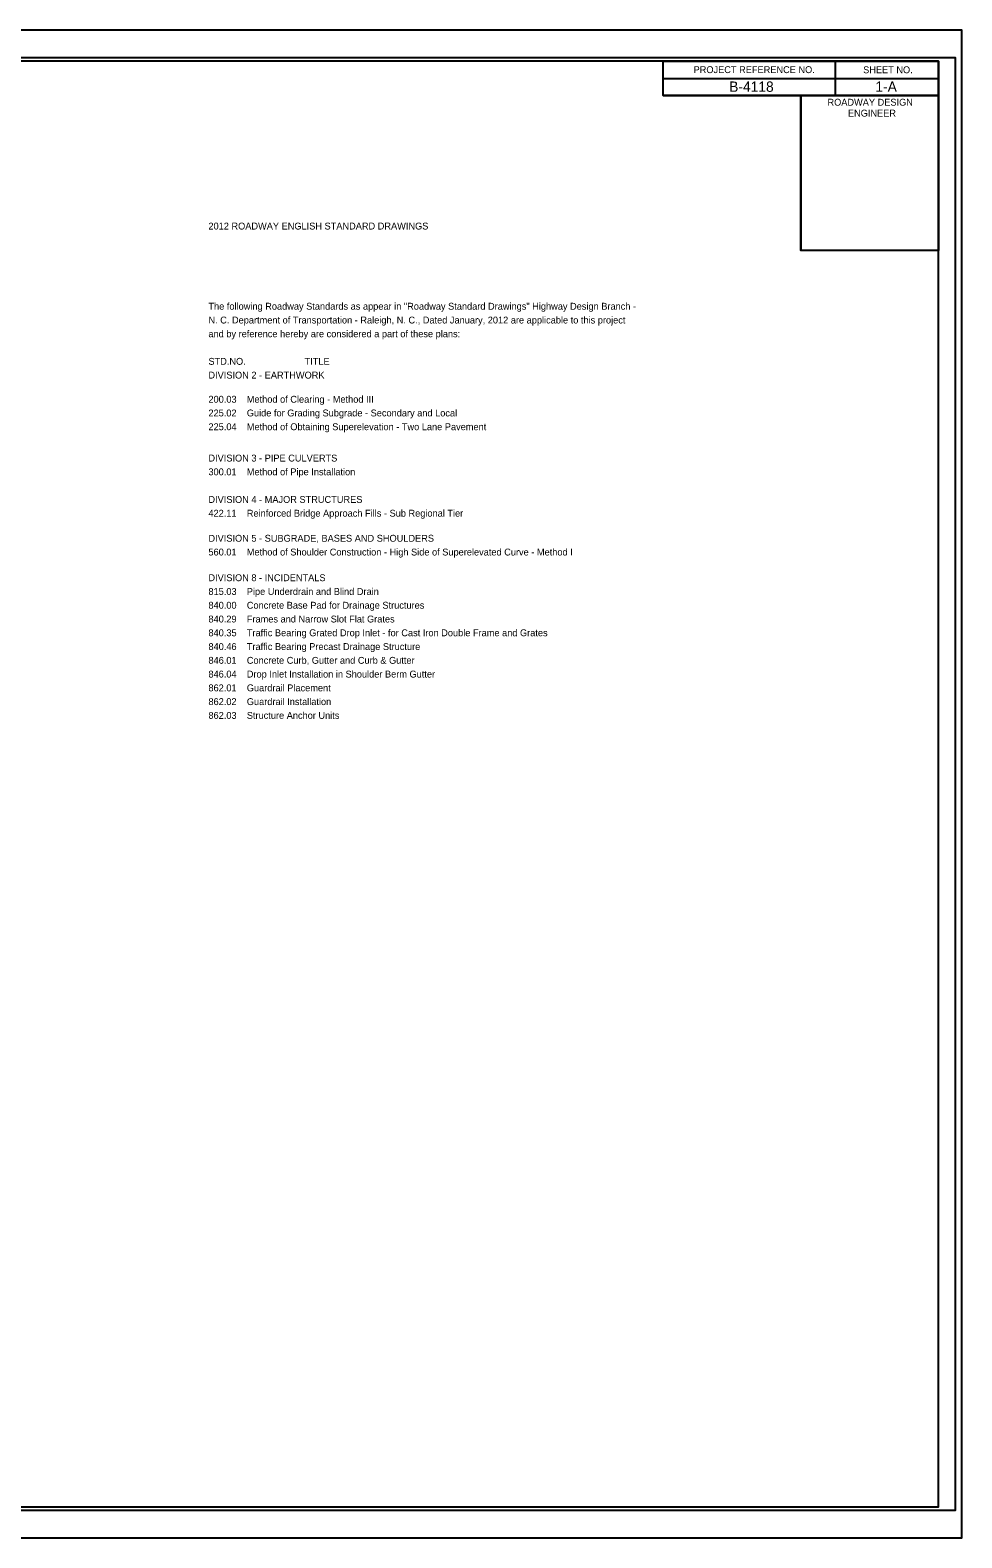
# Model space of a CAD drawing. Extents: x 573853.4 to 573887.1, y -53299.2 to -53277.3.
# Drawn here: x 573873.53 to 573887.06, y -53299.24 to -53277.34 of the extents above; entities that cross this region are included whole.
import ezdxf

# ---------------------------------------------------------------- set-up
doc = ezdxf.new("R2010")
doc.units = 0
for name, color, linetype in [('Prop Dimension Text', 7, 'Continuous'), ('Sheet Cutting Line CELL', 7, 'Continuous'), ('Sheet Data Field CELL', 7, 'Continuous'), ('Sheet Plan CELL', 7, 'Continuous'), ('Sheet Plot Border Inside CELL', 7, 'Continuous'), ('Sheet Plot Border Outside CELL', 7, 'Continuous')]:
    doc.layers.add(name, color=color, linetype=linetype)

msp = doc.modelspace()

# ---------------------------------------------------------------- linework, layer by layer
at = {"layer": 'Sheet Cutting Line CELL'}
for p, q in [((573887.06, -53277.34), (573853.39, -53277.34)), ((573853.39, -53299.24), (573887.06, -53299.24))]:
    msp.add_line(p, q, dxfattribs=at)
at = {"layer": 'Sheet Plan CELL'}
for p, q in [((573885.22, -53277.791), (573885.22, -53278.291)), ((573882.719, -53278.041), (573886.72, -53278.041)), ((573882.719, -53278.291), (573886.72, -53278.291)), ((573882.719, -53278.291), (573886.72, -53278.291)), ((573884.72, -53278.291), (573884.72, -53280.54))]:
    msp.add_line(p, q, dxfattribs=at)
for points in [[(573886.72, -53277.79), (573856.72, -53277.79), (573856.72, -53298.79), (573886.72, -53298.79)], [(573882.719, -53277.79), (573886.72, -53277.79), (573886.72, -53278.291), (573882.719, -53278.291)], [(573884.72, -53278.291), (573886.72, -53278.291), (573886.72, -53280.541), (573884.72, -53280.541)]]:
    msp.add_lwpolyline(points, close=True, dxfattribs=at)
at = {"layer": 'Sheet Plot Border Inside CELL'}
msp.add_lwpolyline([(573853.65, -53298.84), (573886.97, -53298.84), (573886.97, -53277.74), (573853.65, -53277.74)], close=True, dxfattribs=at)
at = {"layer": 'Sheet Plot Border Outside CELL'}
msp.add_lwpolyline([(573853.39, -53299.24), (573887.06, -53299.24), (573887.06, -53277.34), (573853.39, -53277.34)], close=True, dxfattribs=at)

# ---------------------------------------------------------------- texts
at = {"layer": 'Prop Dimension Text'}
for s, p in [('2012 ROADWAY ENGLISH STANDARD DRAWINGS', (573876.115, -53280.236)), ('The following Roadway Standards as appear in "Roadway Standard Drawings" Highway Design Branch -', (573876.115, -53281.401)), ('N. C. Department of Transportation - Raleigh, N. C., Dated January, 2012 are applicable to this project', (573876.115, -53281.601)), ('and by reference hereby are considered a part of these plans:', (573876.115, -53281.801)), ('STD.NO.                       TITLE', (573876.115, -53282.201)), ('DIVISION 2 - EARTHWORK', (573876.115, -53282.401)), ('200.03    Method of Clearing - Method III', (573876.115, -53282.752)), ('225.02    Guide for Grading Subgrade - Secondary and Local', (573876.115, -53282.951)), ('225.04    Method of Obtaining Superelevation - Two Lane Pavement', (573876.115, -53283.151)), ('DIVISION 3 - PIPE CULVERTS', (573876.115, -53283.606)), ('300.01    Method of Pipe Installation ', (573876.115, -53283.806)), ('DIVISION 4 - MAJOR STRUCTURES', (573876.115, -53284.207)), ('422.11    Reinforced Bridge Approach Fills - Sub Regional Tier', (573876.115, -53284.407)), ('DIVISION 5 - SUBGRADE, BASES AND SHOULDERS', (573876.115, -53284.771)), ('560.01    Method of Shoulder Construction - High Side of Superelevated Curve - Method I', (573876.115, -53284.971)), ('DIVISION 8 - INCIDENTALS', (573876.115, -53285.344)), ('815.03    Pipe Underdrain and Blind Drain', (573876.115, -53285.544)), ('840.00    Concrete Base Pad for Drainage Structures', (573876.115, -53285.744)), ('840.29    Frames and Narrow Slot Flat Grates', (573876.115, -53285.944)), ('840.35    Traffic Bearing Grated Drop Inlet - for Cast Iron Double Frame and Grates', (573876.115, -53286.144)), ('840.46    Traffic Bearing Precast Drainage Structure', (573876.115, -53286.344)), ('846.01    Concrete Curb, Gutter and Curb & Gutter', (573876.115, -53286.544)), ('846.04    Drop Inlet Installation in Shoulder Berm Gutter', (573876.115, -53286.744)), ('862.01    Guardrail Placement', (573876.115, -53286.944)), ('862.02    Guardrail Installation', (573876.115, -53287.144)), ('862.03    Structure Anchor Units', (573876.115, -53287.344))]:
    msp.add_text(s, height=0.1, dxfattribs=at).set_placement(p)
at = {"layer": 'Sheet Data Field CELL'}
for s, p in [('B-4118', (573883.68, -53278.236)), ('1-A', (573885.804, -53278.235))]:
    msp.add_text(s, height=0.15, dxfattribs=at).set_placement(p)
at = {"layer": 'Sheet Plan CELL'}
for s, p in [('PROJECT REFERENCE NO.', (573883.163, -53277.964)), ('SHEET NO.', (573885.626, -53277.966)), ('ROADWAY DESIGN', (573885.108, -53278.437)), ('ENGINEER', (573885.405, -53278.596))]:
    msp.add_text(s, height=0.1, dxfattribs=at).set_placement(p)

doc.saveas('drawing.dxf')
